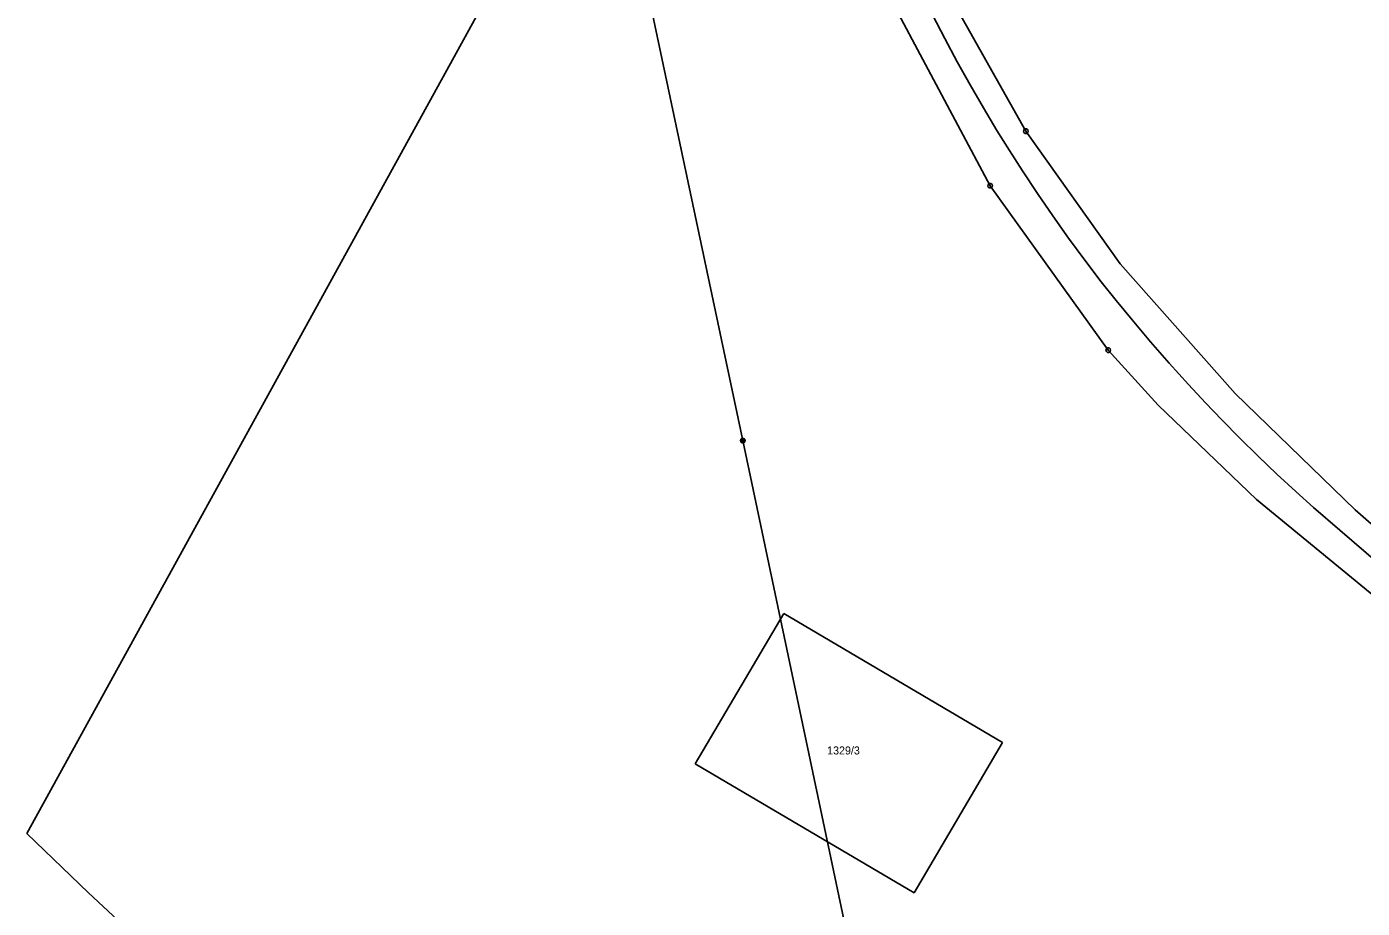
# Model space of a CAD drawing. Extents: x -789470 to -786707, y -1118640 to -1114455.
# Drawn here: x -787858.4 to -787574.7, y -1117025.8 to -1116838.5 of the extents above; entities that cross this region are included whole.
import ezdxf

# ---------------------------------------------------------------- set-up
doc = ezdxf.new("R2010")
doc.units = 0
for name, color, linetype in [('1', 7, 'Continuous'), ('2', 7, 'Continuous'), ('6', 7, 'Continuous'), ('8', 7, 'Continuous')]:
    doc.layers.add(name, color=color, linetype=linetype)

msp = doc.modelspace()

# ---------------------------------------------------------------- linework, layer by layer
at = {"layer": '1'}
for p, q in [((-787707.44, -1116735.64), (-787858.42, -1117009.87)), ((-787646.12, -1116860.74), (-787663.57, -1116829.76)), ((-787674.36, -1116833.72), (-787653.7, -1116872.34)), ((-787626.1, -1116888.93), (-787646.12, -1116860.74)), ((-787653.7, -1116872.34), (-787628.62, -1116907.25)), ((-787601.65, -1116916.45), (-787626.1, -1116888.93)), ((-787628.62, -1116907.25), (-787618.03, -1116918.91)), ((-787576.19, -1116941.14), (-787601.65, -1116916.45)), ((-787618.03, -1116918.91), (-787597.14, -1116938.99)), ((-787597.14, -1116938.99), (-787530.85, -1116993.38)), ((-787576.19, -1116941.14), (-787514.87, -1116995.01)), ((-787697.59, -1116963.17), (-787716.41, -1116995.09)), ((-787651.09, -1116990.59), (-787697.59, -1116963.17)), ((-787669.9, -1117022.51), (-787651.09, -1116990.59)), ((-787716.41, -1116995.09), (-787669.9, -1117022.51)), ((-787858.42, -1117009.87), (-787845.29, -1117022.51)), ((-787845.29, -1117022.51), (-787796.95, -1117067.42))]:
    msp.add_line(p, q, dxfattribs=at)
at = {"layer": '6'}
for p, q in [((-787706.26, -1116926.46), (-787728.61, -1116820.94)), ((-787684.51, -1117029.53), (-787706.26, -1116926.46)), ((-787585.05, -1116940.64), (-787517.82, -1116998.57))]:
    msp.add_line(p, q, dxfattribs=at)
for points in [[(-787668.17, -1116831.52), (-787665.94, -1116836.02), (-787663.36, -1116841.02), (-787660.71, -1116845.97), (-787657.98, -1116850.88), (-787655.16, -1116855.74), (-787652.27, -1116860.56), (-787649.62, -1116864.83), (-787646.87, -1116869.14), (-787643.67, -1116873.96), (-787640.4, -1116878.73), (-787637.04, -1116883.45), (-787633.61, -1116888.11), (-787630.1, -1116892.71), (-787626.94, -1116896.72)], [(-787626.94, -1116896.72), (-787623.57, -1116900.83), (-787619.65, -1116905.46), (-787615.66, -1116910.03), (-787611.59, -1116914.53), (-787607.96, -1116918.41), (-787604.49, -1116922.04), (-787600.65, -1116925.93), (-787596.75, -1116929.77), (-787592.79, -1116933.56), (-787588.78, -1116937.28), (-787585.05, -1116940.64)], [(-787706.41, -1116925.98), (-787706.1, -1116925.98), (-787705.85, -1116926.16), (-787705.75, -1116926.45), (-787705.85, -1116926.74), (-787706.1, -1116926.92), (-787706.41, -1116926.92), (-787706.66, -1116926.74), (-787706.76, -1116926.45), (-787706.66, -1116926.16), (-787706.41, -1116925.98), (-787706.38, -1116926.02), (-787706.14, -1116926.02), (-787705.98, -1116926.1), (-787706.54, -1116926.1), (-787706.62, -1116926.18), (-787705.9, -1116926.18), (-787705.9, -1116926.26), (-787706.62, -1116926.26), (-787706.66, -1116926.34), (-787705.86, -1116926.34), (-787705.82, -1116926.42), (-787706.7, -1116926.42), (-787706.7, -1116926.5), (-787705.82, -1116926.5), (-787705.85, -1116926.58), (-787706.66, -1116926.58), (-787706.65, -1116926.66), (-787705.84, -1116926.66), (-787705.89, -1116926.74), (-787706.61, -1116926.74), (-787706.53, -1116926.82), (-787705.97, -1116926.82), (-787706.08, -1116926.9), (-787706.42, -1116926.9)]]:
    msp.add_lwpolyline(points, dxfattribs=at)
at = {"layer": '8'}
for p, q in [((-787646.24, -1116860.74), (-787646, -1116860.74)), ((-787653.82, -1116872.34), (-787653.58, -1116872.34)), ((-787628.74, -1116907.25), (-787628.5, -1116907.25))]:
    msp.add_line(p, q, dxfattribs=at)
for points in [[(-787645.97, -1116860.26), (-787645.72, -1116860.44), (-787645.62, -1116860.73), (-787645.72, -1116861.02), (-787645.97, -1116861.2), (-787646.28, -1116861.2), (-787646.53, -1116861.02), (-787646.63, -1116860.73), (-787646.53, -1116860.44), (-787646.28, -1116860.26)], [(-787653.55, -1116871.86), (-787653.3, -1116872.04), (-787653.2, -1116872.33), (-787653.3, -1116872.62), (-787653.55, -1116872.8), (-787653.86, -1116872.8), (-787654.11, -1116872.62), (-787654.21, -1116872.33), (-787654.11, -1116872.04), (-787653.86, -1116871.86)], [(-787628.47, -1116906.77), (-787628.22, -1116906.95), (-787628.12, -1116907.24), (-787628.22, -1116907.53), (-787628.47, -1116907.71), (-787628.78, -1116907.71), (-787629.03, -1116907.53), (-787629.13, -1116907.24), (-787629.03, -1116906.95), (-787628.78, -1116906.77)]]:
    msp.add_lwpolyline(points, close=True, dxfattribs=at)

# ---------------------------------------------------------------- texts
at = {"layer": '2'}
msp.add_text('1329/3', height=1.7, dxfattribs=at).set_placement((-787688.36, -1116993.11))

doc.saveas('drawing.dxf')
